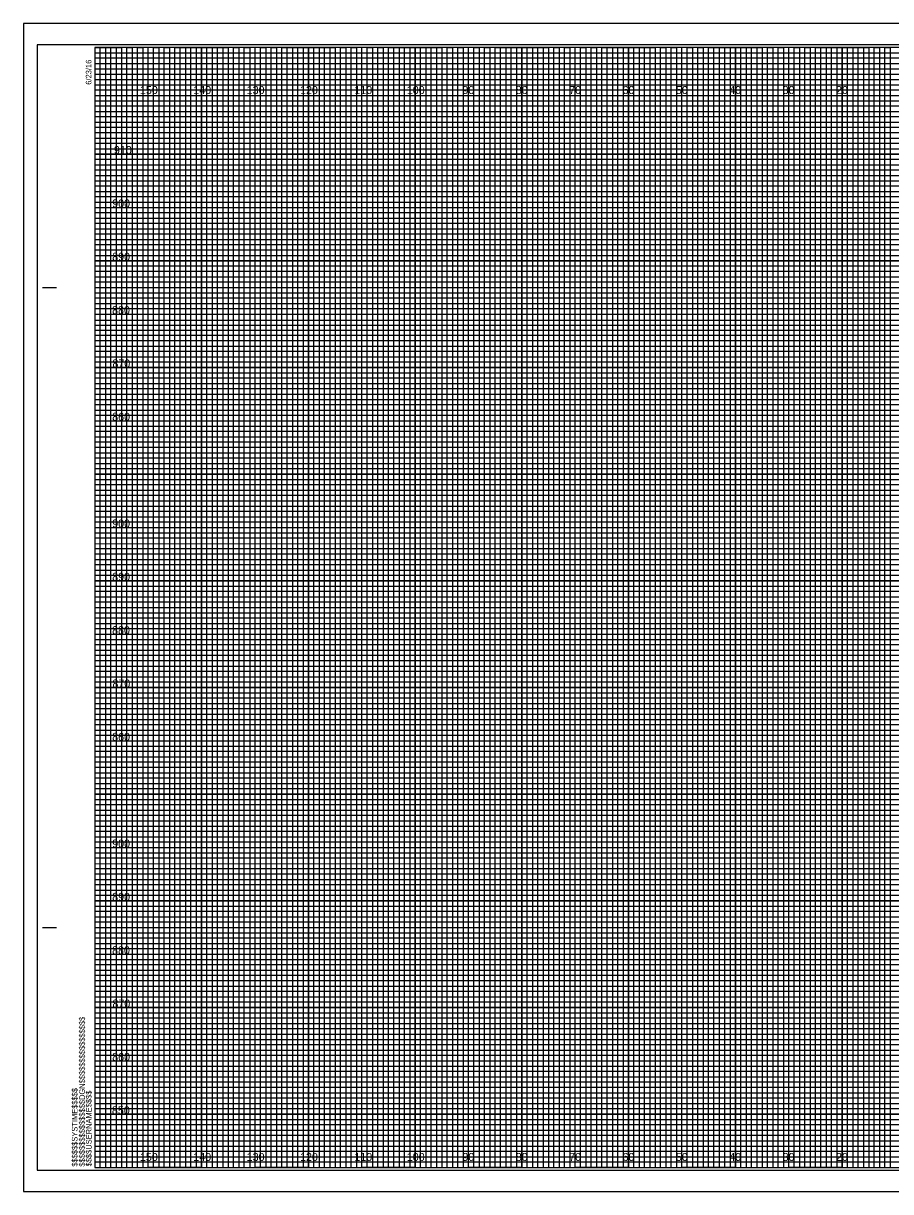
# Model space of a CAD drawing. Extents: x -13 to 323, y 876 to 1094.
# Drawn here: x -13.4 to 149.1, y 875.5 to 1094.5 of the extents above; entities that cross this region are included whole.
import ezdxf

# ---------------------------------------------------------------- set-up
doc = ezdxf.new("R2010")
doc.units = 0
for name, color, linetype in [('Prop XS Elevation Labels', 7, 'Continuous'), ('Prop XS Shear Point Element', 7, 'Continuous'), ('Scratch_Level_4', 7, 'Continuous'), ('Sheet Cross Section CELL', 7, 'Continuous'), ('Sheet Cross Section Grid Middle CELL', 7, 'Continuous'), ('Sheet Cross Section Grid Minor 1 CELL', 7, 'Continuous'), ('Sheet Cross Section Grid Minor 2 CELL', 7, 'Continuous'), ('Sheet Cutting Line CELL', 7, 'Continuous'), ('Sheet DOT Grid CELL', 7, 'Continuous'), ('Sheet Plot Border Inside CELL', 7, 'Continuous'), ('Sheet Plot Border Outside CELL', 7, 'Continuous')]:
    doc.layers.add(name, color=color, linetype=linetype)

msp = doc.modelspace()

# ---------------------------------------------------------------- linework, layer by layer
at = {"layer": 'Scratch_Level_4'}
for p, q in [((10, 1090), (0, 1090)), ((10, 880), (10, 1090)), ((30, 1090), (20, 1090)), ((20, 1090), (20, 880)), ((30, 880), (30, 1090)), ((50, 1090), (40, 1090)), ((40, 1090), (40, 880)), ((50, 880), (50, 1090)), ((70, 1090), (60, 1090)), ((60, 1090), (60, 880)), ((70, 880), (70, 1090)), ((90, 1090), (80, 1090)), ((80, 1090), (80, 880)), ((90, 880), (90, 1090)), ((110, 1090), (100, 1090)), ((100, 1090), (100, 880)), ((110, 880), (110, 1090)), ((130, 1090), (120, 1090)), ((120, 1090), (120, 880)), ((130, 880), (130, 1090)), ((150, 1090), (140, 1090)), ((140, 1090), (140, 880)), ((20, 880), (10, 880)), ((40, 880), (30, 880)), ((60, 880), (50, 880)), ((80, 880), (70, 880)), ((100, 880), (90, 880)), ((120, 880), (110, 880)), ((140, 880), (130, 880))]:
    msp.add_line(p, q, dxfattribs=at)
for points in [[(0, 1080), (320, 1080), (320, 1070), (0, 1070)], [(0, 1060), (320, 1060), (320, 1050), (0, 1050)], [(0, 1040), (320, 1040), (320, 1030), (0, 1030)], [(0, 1020), (320, 1020), (320, 1010), (0, 1010)], [(0, 1000), (320, 1000), (320, 990), (0, 990)], [(0, 980), (320, 980), (320, 970), (0, 970)], [(0, 960), (320, 960), (320, 950), (0, 950)], [(0, 940), (320, 940), (320, 930), (0, 930)], [(0, 920), (320, 920), (320, 910), (0, 910)], [(0, 900), (320, 900), (320, 890), (0, 890)]]:
    msp.add_lwpolyline(points, dxfattribs=at)
at = {"layer": 'Sheet Cross Section CELL'}
for p, q in [((-9.8, 1045), (-7.3, 1045)), ((-9.7, 1045), (-7.2, 1045)), ((-9.8, 925), (-7.3, 925)), ((-9.7, 925), (-7.2, 925)), ((0, 880), (0, 880)), ((0, 880), (0, 880)), ((0, 880), (0, 880)), ((0, 880), (0, 880)), ((0, 880), (0, 880)), ((0, 880), (0, 880)), ((0, 880), (0, 880))]:
    msp.add_line(p, q, dxfattribs=at)
msp.add_lwpolyline([(320, 1090), (0, 1090), (0, 880), (320, 880)], close=True, dxfattribs=at)
at = {"layer": 'Sheet Cross Section Grid Middle CELL'}
for points in [[(0, 1090), (5, 1090), (5, 880), (15, 880), (15, 1090), (25, 1090), (25, 880), (35, 880), (35, 1090), (45, 1090), (45, 880), (55, 880), (55, 1090), (65, 1090), (65, 880), (75, 880), (75, 1090), (85, 1090), (85, 880), (95, 880), (95, 1090), (105, 1090), (105, 880), (115, 880), (115, 1090), (125, 1090), (125, 880), (135, 880), (135, 1090), (145, 1090), (145, 880), (155, 880)], [(0, 1085), (275, 1085)], [(0, 1065), (320, 1065), (320, 1075), (0, 1075)], [(0, 1045), (320, 1045), (320, 1055), (0, 1055)], [(0, 1025), (320, 1025), (320, 1035), (0, 1035)], [(0, 1005), (320, 1005), (320, 1015), (0, 1015)], [(0, 985), (320, 985), (320, 995), (0, 995)], [(0, 965), (320, 965), (320, 975), (0, 975)], [(0, 945), (320, 945), (320, 955), (0, 955)], [(0, 925), (320, 925), (320, 935), (0, 935)], [(0, 905), (320, 905), (320, 915), (0, 915)], [(0, 885), (320, 885), (320, 895), (0, 895)]]:
    msp.add_lwpolyline(points, dxfattribs=at)
at = {"layer": 'Sheet Cross Section Grid Minor 1 CELL'}
for p, q in [((0, 1089), (260, 1089)), ((260, 1087.98), (0, 1087.98)), ((0, 1087.98), (0, 1087)), ((0, 1087), (260, 1087)), ((260, 1085.89), (0, 1085.89)), ((0, 1085.89), (0, 1084)), ((0, 1084), (320, 1084))]:
    msp.add_line(p, q, dxfattribs=at)
for points in [[(0, 1083), (270, 1083), (320, 1083), (320, 1082), (0, 1082)], [(0, 1081), (320, 1081), (320, 1079), (0, 1079)], [(0, 1078), (320, 1078), (320, 1077), (0, 1076.98)], [(0, 1076), (320, 1076), (320, 1074), (0, 1074)], [(0, 1073), (320, 1073), (320, 1072), (0, 1072)], [(0, 1071), (320, 1071), (320, 1069), (0, 1069)], [(0, 1068), (320, 1068), (320, 1067), (0, 1067)], [(0, 1066), (320, 1066), (320, 1064), (0, 1064)], [(0, 1063), (320, 1063), (320, 1062), (0, 1062)], [(0, 1061), (320, 1061), (320, 1059), (0, 1059)], [(0, 1058), (320, 1058), (320, 1057), (0, 1057)], [(0, 1056), (320, 1056), (320, 1053.95), (320, 1053), (320, 1052), (0, 1052)], [(0, 1054), (320, 1054), (320, 1053), (0, 1053)], [(0, 1051), (320, 1051), (320, 1049), (0, 1049.03)], [(0, 1049.03), (320, 1049), (320, 1048), (0, 1048)], [(0, 1047), (320, 1047), (320, 1046), (0, 1046)], [(0, 1044), (320, 1044), (320, 1043), (0, 1043)], [(0, 1042), (320, 1042), (320, 1041), (0, 1041)], [(-0.07, 1038.89), (320, 1038.89), (320, 1037.88), (-0.07, 1037.88)], [(0, 1037), (320, 1037), (320, 1036), (0, 1036)], [(0, 1034), (320, 1034), (320, 1033), (0, 1033)], [(0, 1032), (320, 1032), (320, 1031), (0, 1031)], [(0, 1029), (320, 1029), (320, 1028), (0, 1028)], [(0, 1027), (320, 1027), (320, 1026), (0, 1026)], [(0, 1024), (320, 1024), (320, 1023), (0, 1023)], [(0, 1022), (320, 1022), (320, 1021), (0, 1021)], [(0, 1019), (320, 1019), (319.99, 1017.98), (0, 1018)], [(0, 1017), (320, 1017), (320, 1016), (0, 1016)], [(0, 1014), (320, 1014), (320, 1013), (0, 1013)], [(0, 1012), (320, 1012), (320, 1011), (0, 1011)], [(0, 1009), (320, 1009), (320, 1008), (0, 1008)], [(0, 1007), (320, 1007), (320, 1006), (0, 1006)], [(0, 1004), (320, 1004), (320, 1003), (0, 1003)], [(0, 1002), (320, 1002), (320, 1001), (0, 1001)], [(0, 999), (320, 999), (320, 998), (0, 998)], [(0, 996.99), (320.07, 996.91), (320, 996), (0, 996)], [(0, 994), (320, 994), (320, 993), (0, 993)], [(0, 992), (320, 992), (320, 991), (0, 991)], [(0, 989), (320, 989), (320, 988), (0, 988)], [(0, 987), (320, 987), (320, 986), (0, 986)], [(0, 984), (320, 984), (320, 983), (0, 983)], [(0, 982), (320, 982), (320, 981), (0, 981)], [(0, 979), (320, 979), (320, 978), (0, 978)], [(0, 977), (320, 977), (320, 976), (0, 976)], [(0, 974), (320, 974), (320, 973), (0, 973)], [(0, 972), (320, 972), (320, 971), (0, 971)], [(0, 969), (320, 969), (320, 968), (0, 968)], [(0, 967), (320, 967), (320, 966), (0, 966)], [(0, 964), (320, 964), (320, 963), (0, 963)], [(0, 962), (320, 962), (320, 961), (0, 961)], [(0, 959), (320, 959), (319.99, 957.98), (0, 958)], [(0, 957), (320, 957), (320, 956), (0, 956)], [(0, 954), (320, 954), (320, 953), (0, 953)], [(0, 952), (320, 952), (320, 951), (0, 951)], [(0, 949), (320, 949), (320, 948), (0, 948)], [(0, 947), (320, 947), (320, 946), (0, 946)], [(0, 944), (320, 944), (320, 943), (0, 943)], [(0, 942), (320, 942), (320, 941), (0, 941)], [(0, 939), (320, 939), (320, 938), (0, 938)], [(0, 936.99), (320.07, 936.91), (320, 936), (0, 936)], [(0, 934), (320, 934), (320, 933), (0, 933)], [(0, 932), (320, 932), (320, 931), (0, 931)], [(0, 929), (320, 929), (320, 928), (0, 928)], [(0, 927), (320, 927), (320, 926), (0, 926)], [(0, 924), (320, 924), (320, 923), (0, 923)], [(0, 922), (320, 922), (320, 921), (0, 921)], [(0, 919), (320, 919), (320, 918), (0, 918)], [(0, 917), (320, 917), (320, 916), (0, 916)], [(0, 914), (320, 914), (320, 913), (0, 913)], [(0, 912), (320, 912), (320, 911), (0, 911)], [(0, 909), (320, 909), (320, 908), (0, 908)], [(0, 907), (320, 907), (320, 906), (0, 906)], [(0, 904), (320, 904), (320, 903), (0, 903)], [(0, 902), (320, 902), (320, 901), (0, 901)], [(0, 899), (320, 899), (320, 898), (0, 898)], [(0, 897), (320, 897), (320, 896), (0, 896)], [(0, 894), (320, 894), (320, 893), (0, 893)], [(0, 892), (320, 892), (320, 891), (0, 891)], [(0, 889), (320, 889), (320, 888), (0, 888)], [(0, 887), (320, 887), (320, 886), (0, 886)], [(0, 884), (320, 884), (320, 883), (0, 883)], [(0, 882), (320, 882), (320, 881), (0, 881)]]:
    msp.add_lwpolyline(points, dxfattribs=at)
at = {"layer": 'Sheet Cross Section Grid Minor 2 CELL'}
for points in [[(0, 880), (1, 880), (1, 1090), (2, 1090), (2, 880)], [(2, 880), (3, 880), (3, 1090), (4, 1090), (4, 880)], [(5, 880), (6, 880), (6, 1090), (7, 1090), (7, 880)], [(7, 880), (8, 880), (8, 1090), (9, 1090), (9, 880)], [(10, 880), (11, 880), (11, 1090), (12, 1090), (12, 880)], [(12, 880), (13, 880), (13, 1090), (14, 1090), (14, 880)], [(15, 880), (16, 880), (16, 1090), (17, 1090), (17, 880)], [(17, 880), (18, 880), (18, 1090), (19, 1090), (19, 880)], [(20, 880), (21, 880), (21, 1090), (22, 1090), (22, 880)], [(22, 880), (23, 880), (23, 1090), (24, 1090), (24, 880)], [(25, 880), (26, 880), (26, 1090), (27, 1090), (27, 880)], [(27, 880), (28, 880), (28, 1090), (29, 1090), (29, 880)], [(30, 880), (31, 880), (31, 1090), (32, 1090), (32, 880)], [(32, 880), (33, 880), (33, 1090), (34, 1090), (34, 880)], [(35, 880), (36, 880), (36, 1090), (37, 1090), (37, 880)], [(37, 880), (38, 880), (38, 1090), (39, 1090), (39, 880)], [(40, 880), (41, 880), (41, 1090), (42, 1090), (42, 880)], [(42, 880), (43, 880), (43, 1090), (44, 1090), (44, 880)], [(45, 880), (46, 880), (46, 1090), (47, 1090), (47, 880)], [(47, 880), (48, 880), (48, 1090), (49, 1090), (49, 880)], [(50, 880), (51, 880), (51, 1090), (52, 1090), (52, 880)], [(52, 880), (53, 880), (53, 1090), (54, 1090), (54, 880)], [(55, 880), (56, 880), (56, 1090), (57, 1090), (57, 880)], [(57, 880), (58, 880), (58, 1090), (59, 1090), (59, 880)], [(60, 880), (61, 880), (61, 1090), (62, 1090), (62, 880)], [(62, 880), (63, 880), (63, 1090), (64, 1090), (64, 880)], [(65, 880), (66, 880), (66, 1090), (67, 1090), (67, 880)], [(67, 880), (68, 880), (68, 1090), (69, 1090), (69, 880)], [(70, 880), (71, 880), (71, 1090), (72, 1090), (72, 880)], [(72, 880), (73, 880), (73, 1090), (74, 1090), (74, 880)], [(75, 880), (76, 880), (76, 1090), (77, 1090), (77, 880)], [(77, 880), (78, 880), (78, 1090), (79, 1090), (79, 880)], [(80, 880), (81, 880), (81, 1090), (82, 1090), (82, 880)], [(82, 880), (83, 880), (83, 1090), (84, 1090), (84, 880)], [(85, 880), (86, 880), (86, 1090), (87, 1090), (87, 880)], [(87, 880), (88, 880), (88, 1090), (89, 1090), (89, 880)], [(90, 880), (91, 880), (91, 1090), (92, 1090), (92, 880)], [(92, 880), (93, 880), (93, 1090), (94, 1090), (94, 880)], [(95, 880), (96, 880), (96, 1090), (97, 1090), (97, 880)], [(97, 880), (98, 880), (98, 1090), (99, 1090), (99, 880)], [(100, 880), (101, 880), (101, 1090), (102, 1090), (102, 880)], [(102, 880), (103, 880), (103, 1090), (104, 1090), (104, 880)], [(105, 880), (106, 880), (106, 1090), (107, 1090), (107, 880)], [(107, 880), (108, 880), (108, 1090), (109, 1090), (109, 880)], [(110, 880), (111, 880), (111, 1090), (112, 1090), (112, 880)], [(112, 880), (113, 880), (113, 1090), (114, 1090), (114, 880)], [(115, 880), (116, 880), (116, 1090), (117, 1090), (117, 880)], [(117, 880), (118, 880), (118, 1090), (119, 1090), (119, 880)], [(120, 880), (121, 880), (121, 1090), (122, 1090), (122, 880)], [(122, 880), (123, 880), (123, 1090), (124, 1090), (124, 880)], [(125, 880), (126, 880), (126, 1090), (127, 1090), (127, 880)], [(127, 880), (128, 880), (128, 1090), (129, 1090), (129, 880)], [(130, 880), (131, 880), (131, 1090), (132, 1090), (132, 880)], [(132, 880), (133, 880), (133, 1090), (134, 1090), (134, 880)], [(135, 880), (136, 880), (136, 1090), (137, 1090), (137, 880)], [(137, 880), (138, 880), (138, 1090), (139, 1090), (139, 880)], [(140, 880), (141, 880), (141, 1090), (142, 1090), (142, 880)], [(142, 880), (143, 880), (143, 1090), (144, 1090), (144, 880)], [(145, 880), (146, 880), (146, 1090), (147, 1090), (147, 880)], [(147, 880), (148, 880), (148, 1090), (149, 1090), (149, 880)]]:
    msp.add_lwpolyline(points, dxfattribs=at)
at = {"layer": 'Sheet Cutting Line CELL'}
for p, q in [((323.3, 1094.5), (-13.4, 1094.5)), ((-13.4, 1094.5), (-13.4, 875.5)), ((-13.4, 875.5), (323.3, 875.5))]:
    msp.add_line(p, q, dxfattribs=at)
at = {"layer": 'Sheet DOT Grid CELL'}
for p, q in [((10, 880), (10, 1090)), ((20, 880), (20, 1090)), ((30, 880), (30, 1090)), ((40, 880), (40, 1090)), ((50, 880), (50, 1090)), ((60, 880), (60, 1090)), ((70, 880), (70, 1090)), ((80, 880), (80, 1090)), ((90, 880), (90, 1090)), ((100, 880), (100, 1090)), ((110, 880), (110, 1090)), ((120, 880), (120, 1090)), ((130, 880), (130, 1090)), ((140, 880), (140, 1090)), ((0, 1080), (320, 1080)), ((0, 1070), (320, 1070)), ((0, 1060), (320, 1060)), ((0, 1050), (320, 1050)), ((0, 1040), (320, 1040)), ((0, 1030), (320, 1030)), ((0, 1020), (320, 1020)), ((0, 1010), (320, 1010)), ((0, 1000), (320, 1000)), ((0, 990), (320, 990)), ((0, 980), (320, 980)), ((0, 970), (320, 970)), ((0, 960), (320, 960)), ((0, 950), (320, 950)), ((0, 940), (320, 940)), ((0, 930), (320, 930)), ((0, 920), (320, 920)), ((0, 910), (320, 910)), ((0, 900), (320, 900)), ((0, 890), (320, 890))]:
    msp.add_line(p, q, dxfattribs=at)
at = {"layer": 'Sheet Plot Border Inside CELL'}
msp.add_lwpolyline([(-10.8, 879.5), (322.4, 879.5), (322.4, 1090.5), (-10.8, 1090.5)], close=True, dxfattribs=at)
at = {"layer": 'Sheet Plot Border Outside CELL'}
msp.add_lwpolyline([(-13.4, 875.5), (323.3, 875.5), (323.3, 1094.5), (-13.4, 1094.5)], close=True, dxfattribs=at)

# ---------------------------------------------------------------- texts
at = {"layer": 'Prop XS Elevation Labels'}
for s, p in [('910', (3.57, 1070)), ('900', (3.24, 1060)), ('890', (3.24, 1050)), ('880', (3.22, 1040)), ('870', (3.28, 1030)), ('860', (3.24, 1020)), ('900', (3.24, 1000)), ('890', (3.24, 990)), ('880', (3.22, 980)), ('870', (3.28, 970)), ('860', (3.24, 960)), ('900', (3.24, 940)), ('890', (3.24, 930)), ('880', (3.22, 920)), ('870', (3.28, 910)), ('860', (3.24, 900)), ('850', (3.19, 890))]:
    msp.add_text(s, height=1.5, dxfattribs=at).set_placement(p)
at = {"layer": 'Prop XS Shear Point Element'}
for s, p in [('150', (8.44, 1081.25)), ('140', (18.44, 1081.25)), ('130', (28.44, 1081.25)), ('120', (38.44, 1081.25)), ('110', (48.62, 1081.25)), ('100', (58.44, 1081.25)), ('90', (68.86, 1081.25)), ('80', (78.86, 1081.25)), ('70', (88.86, 1081.25)), ('60', (98.86, 1081.25)), ('50', (108.86, 1081.25)), ('40', (118.86, 1081.25)), ('30', (128.86, 1081.25)), ('20', (138.86, 1081.25)), ('150', (8.44, 881.25)), ('140', (18.44, 881.25)), ('130', (28.44, 881.25)), ('120', (38.44, 881.25)), ('110', (48.62, 881.25)), ('100', (58.44, 881.25)), ('90', (68.86, 881.25)), ('80', (78.86, 881.25)), ('70', (88.86, 881.25)), ('60', (98.86, 881.25)), ('50', (108.86, 881.25)), ('40', (118.86, 881.25)), ('30', (128.86, 881.25)), ('20', (138.86, 881.25))]:
    msp.add_text(s, height=1.5, dxfattribs=at).set_placement(p)
at = {"layer": 'Sheet Cross Section CELL'}
for s, p in [('6/23/16', (-0.65, 1083)), ('$$$$$$$$$$$$$$$$DGN$$$$$$$$$$$$$$$$', (-1.88, 880.18)), ('$$$$$$SYSTIME$$$$$', (-3.26, 880.18)), ('$$$$USERNAME$$$$', (-0.62, 880.23))]:
    msp.add_text(s, height=1.05, rotation=90, dxfattribs=at).set_placement(p)

doc.saveas('drawing.dxf')
